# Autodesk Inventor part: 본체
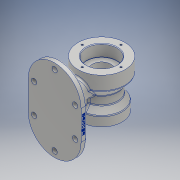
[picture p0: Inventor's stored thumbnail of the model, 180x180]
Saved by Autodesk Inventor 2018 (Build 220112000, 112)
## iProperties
Created: 2020-01
Part Number: 본체
Material: 알루미늄 6061
Document SubType Name: Modeling
Designer: Administrator
Density: 2.7 g/cm^3
Appearance: 알루미늄 - 평지
Mass: 938.111 g
Surface Area: 654.887 cm^2
Volume: 347.449 cm^3
Author: Administrator
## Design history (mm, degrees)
sketch "스케치1"
  geometry: L1 (45, 25)-(45, -25); L2 (-45, 25)-(-45, -25); A1 r 45 centre (0, 25) between (45, 25) and (-45, 25); A2 r 45 centre (0, -25) between (-45, -25) and (45, -25); 1 further point
  constraints: 4 end point, 4 point on circle, 2 centre point, 2 tangent, 2 vertical
  dimensions: "d2" = 45 radius of A1; "d3" = 45 radius of A2
extrude "돌출1" new body sketch "스케치1" distance "d4" = 10; taper "d5" = 0 deg
sketch "스케치2"
  geometry: L1 (45, -25)-(45, 25) reference; L2 (-45, 25)-(-45, -25) reference; L3 (-5, 3.199)-(-5, 30); L4 (5, 3.199)-(5, 30); L5 (0, 30)-(-5, 30); L6 (0, 30)-(5, 30); A1 r 45 centre (0, -25) between (-45, -25) and (45, -25) reference; A2 r 45 centre (0, 25) between (45, 25) and (-45, 25) reference; A3 r 45 centre (0, -25) between (-45, -25) and (45, -25) reference; A4 r 16 centre (0, -12) between (-5, 3.199) and (5, 3.199); 1 further point
  constraints: 8 end point, 2 perpendicular, 2 point on circle, 1 centre point
  dimensions: "d7" = 16 radius of A4
extrude "돌출2" join sketch "스케치2" distance "d13" = 80; taper "d14" = 0 deg
sketch "스케치3"
  geometry: L1 (0, 25)-(0, 70) reference; L2 (0, 70)-(10, 70) reference; L3 (80, 40)-(120, 40); L4 (120, 40)-(120, 16); L5 (80, 40)-(80, -40); L6 (80, -40)-(115, -40); L7 (115, -40)-(115, -24); L8 (120, 16)-(107.5, 1.103); L9 (115, -24)-(107.5, -13.289); L10 (107.5, 1.103)-(107.5, -13.289); L11 (80, 68.012)-(80, -106.966); 1 further point
  constraints: 18 end point, 3 perpendicular, 1 point on line, 1 vertical
  dimensions: "d18" = 40 distance of L3.start L3.end; "d19" = 24 distance of L3.end L4.end; "d20" = 80 distance of L3.start L5.end; "d21" = 35 distance of L5.end L6.end; "d22" = 16 distance of L6.end L7.end; "d23" = 40 deg angle of L4 L8; "d24" = 35 deg angle of L7 L9
revolve "회전1" sketch "스케치3" stored, may be unused: angle "d26" = 90 deg
sketch "스케치4"
  geometry: C1 r 26 at (0, 0); 1 further point
  constraints: 1 centre point
  dimensions: "d27" = 26 radius of C1
extrude "돌출3" cut sketch "스케치4" distance "d28" = 20; taper "d29" = 0 deg
sketch "스케치5"
  geometry: C1 r 16 at (0, 0); 1 further point
  constraints: 1 centre point
  dimensions: "d30" = 16 radius of C1
extrude "돌출4" cut sketch "스케치5" distance "d31" = 100; taper "d32" = 0 deg
sketch "스케치6"
  geometry: C1 r 20 at (0, 0); 1 further point
  constraints: 1 centre point
  dimensions: "d33" = 20 radius of C1
extrude "돌출5" cut sketch "스케치6" distance "d34" = 17; taper "d35" = 0 deg
chamfer "모따기1" distance "d36" = 1; stored, may be unused: second distance "d37" = 2, angle "d38" = 45 deg
fillet "모깎기1" dims "d39" = 3
fillet "모깎기2" dims "d40" = 3
fillet "모깎기3" dims "d41" = 3
fillet "모깎기4" dims "d42" = 3
sketch "스케치7"
  geometry: L1 (-45, 25)-(-45, -25) reference; L2 (45, -25)-(45, 25) reference; L3 (-35, -25)-(-35, 25); L4 (35, -25)-(35, 25); C1 r 4.5 at (-35, -25); C2 r 4.5 at (-35, 25); C3 r 4.5 at (35, 25); C4 r 4.5 at (35, -25); C5 r 4.5 at (0, -60); C6 r 4.5 at (0, 60); A1 r 45 centre (0, -25) between (-45, -25) and (45, -25) reference; A2 r 45 centre (0, 25) between (45, 25) and (-45, 25) reference; A3 r 45 centre (0, 25) between (45, 25) and (-45, 25) reference; A4 r 35 centre (0, 25) between (35, 25) and (-35, 25); A5 r 35 centre (0, -25) between (-35, -25) and (35, -25)
  constraints: 8 centre point, 6 coincident, 6 point on circle, 4 end point, 2 tangent, 2 vertical
  dimensions: "d45" = 4.5 radius of C1; "d46" = 4.5 radius of C2; "d47" = 4.5 radius of C3; "d48" = 4.5 radius of C4; "d49" = 4.5 radius of C5; "d50" = 4.5 radius of C6
extrude "돌출6" cut sketch "스케치7" distance "d51" = 17; taper "d52" = 0 deg
fillet "모깎기5" dims "d53" = 0.3
sketch "스케치8"
  geometry: A1 r 33 centre (0, 0) between (0, 33) and (-33, 0); 3 further points
  constraints: 4 point on circle, 1 centre point
  dimensions: "d54" = 33 radius of A1
hole "구멍1" sketch "스케치8" at (0, 33), (-33, 0), (33, 0), (0, -33) diameter "d55" = 3.242; stored, may be unused: countersink angle "d59" = 90 deg, drill point angle "d61" = 118 deg; dims "d56" = 9, "d57" = 4, "d58" = 2, "d60" = 11
sketch "스케치9"
  geometry: A1 r 27.5 centre (0, 0) between (-13.29, -24.075) and (13.29, -24.075); A2 r 27.5 centre (0, 0) between (13.29, -24.075) and (-13.29, -24.075) reference; 5 further points
  constraints: 4 point on circle, 1 centre point
  dimensions: "d62" = 27.5 radius of A1
hole "구멍2" sketch "스케치9" at (0, 27.5), (-27.5, 0), (27.5, 0), (0, -27.5) diameter "d63" = 3.242; stored, may be unused: countersink angle "d67" = 90 deg, drill point angle "d69" = 118 deg; dims "d64" = 9, "d65" = 4, "d66" = 2, "d68" = 11
sketch "스케치10"
  geometry: L1 (0, 0)-(-45, 0) reference; 2 further points
  constraints: 1 other
  dimensions: "d70" = 4 distance from line of L1 point (25, 4); "d71" = 70 horizontal distance of L1.end point (25, 4)
feature "엠보싱1" sketch "스케치10" dims "d72" = 0.5, "d73" = 0
node "솔리드1"
node "투영된 루프1"
node "투영된 루프2"
